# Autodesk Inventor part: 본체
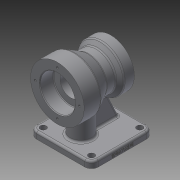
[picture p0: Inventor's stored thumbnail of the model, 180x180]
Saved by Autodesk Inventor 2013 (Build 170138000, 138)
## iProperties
Created: 2019-01
Part Number: 본체
Material: 일반
Document SubType Name: Modeling
Designer: Administrator
Density: 1 g/cm^3
Author: Administrator
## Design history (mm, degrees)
sketch "스케치1"
  geometry: L1 (-30, 0)-(50, 0); L2 (-30, 0)-(-30, 26); L3 (-30, 40)-(-5, 40); L4 (-5, 40)-(15.785, 28); L5 (15.785, 28)-(29.126, 28); L6 (29.126, 28)-(35, 35); L7 (35, 35)-(50, 35); L8 (50, 35)-(50, 20); L9 (-30, 26)-(-10, 26); L10 (-10, 26)-(-10, 16); L11 (-10, 16)-(33, 16); L12 (33, 16)-(33, 20); L13 (33, 20)-(50, 20); L14 (-30, 26)-(-30, 40); L15 (50, 20)-(50, 0); 1 further point
  constraints: 30 end point, 9 perpendicular, 7 parallel, 1 horizontal, 1 point on line
  dimensions: "d0" = 80 distance of L1.start L1.end; "d2" = 80 diameter of L3 L1; "d3" = 30 distance of L1.start point (0, 0); "d4" = 25 distance of L3.start L3.end; "d5" = 52 diameter of L9 L1; "d6" = 20 distance of L2.end L9.end; "d7" = 32 diameter of L11 L1; "d8" = 56 diameter of L5 L1; "d9" = 30 deg angle of L5 L4; "d10" = 50 deg angle of L5 L6; "d11" = 70 diameter of L7 L1; "d12" = 15 distance of L6.end L7.end; "d13" = 40 diameter of L13 L1; "d14" = 17 distance of L12.end L8.end; "d15" = 43 distance of L10.end L11.end
revolve "회전1" sketch "스케치1" stored, may be unused: angle "d16" = 90 deg
sketch "스케치2"
  geometry: C1 r 40 at (0, 0) reference; 1 further point
  constraints: 1 vertical alignment
  dimensions: "d17" = 33 distance of C1.centre point (0, 33)
hole "구멍1" sketch "스케치2" at (0, 33) diameter "d18" = 3.242; stored, may be unused: countersink angle "d22" = 90 deg, drill point angle "d24" = 118 deg; dims "d19" = 9, "d20" = 4, "d21" = 2, "d23" = 11
sketch "스케치3"
  geometry: C1 r 20 at (0, 0) reference; 1 further point
  constraints: 1 vertical alignment
  dimensions: "d28" = 27.5 distance of C1.centre point (0, 27.5)
hole "구멍2" sketch "스케치3" at (0, 27.5) diameter "d29" = 3.242; stored, may be unused: countersink angle "d33" = 90 deg, drill point angle "d35" = 118 deg; dims "d30" = 9, "d31" = 4, "d32" = 2, "d34" = 11
sketch "스케치4"
  geometry: L1 (-25, -70)-(67, -70); L2 (67, -70)-(67, -80); L3 (67, -80)-(-25, -80); L4 (-25, -80)-(-25, -70); 1 further point
  constraints: 8 end point, 2 parallel, 1 horizontal, 1 perpendicular
  dimensions: "d39" = 92 distance of L1.start L1.end; "d41" = 10 distance of L3.end L1.start; "d42" = 80 distance from line of L3 point (0, 0); "d67" = 25 distance from line of point (0, 0) L4
extrude "돌출1" join sketch "스케치4" stored distance "d44" = 92; taper "d45" = 0 deg
fillet "모깎기1" dims "d46" = 10
sketch "스케치5"
  geometry: A1 r 10 centre (72, -10) between (82, -10) and (72, 0) reference; A2 r 10 centre (0, -10) between (0, 0) and (-10, -10) reference; A3 r 10 centre (0, -82) between (-10, -82) and (0, -92) reference; A4 r 10 centre (72, -82) between (72, -92) and (82, -82) reference; 5 further points
  constraints: 4 coincident
hole "구멍3" sketch "스케치5" at (0, -10), (0, -82), (72, -82), (72, -10) diameter "d47" = 9; stored, may be unused: countersink angle "d51" = 90 deg, drill point angle "d53" = 118 deg; dims "d48" = 9, "d49" = 4, "d50" = 2, "d52" = 11
sketch "스케치6"
  geometry: L1 (-10, -10)-(-10, -82) reference; L2 (72, -92)-(0, -92) reference; C1 r 16 at (20, -46); 1 further point
  constraints: 1 centre point
  dimensions: "d68" = 32 diameter of C1; "d70" = 30 distance from line of L1 C1.centre; "d71" = 46 distance from line of C1.centre L2
extrude "돌출2" join sketch "스케치6" stored distance "d56" = 0; taper "d57" = 0 deg
sketch "스케치7"
  geometry: L1 (42.078, -37.999)-(57, -70); L2 (57, -70)-(-15, -70) reference; L3 (67, -80)-(67, -70) reference; L4 (57, -70)-(67, -70) reference; 1 further point
  constraints: 2 end point, 1 point on line
  dimensions: "d58" = 25 deg angle of L1 L3; "d59" = 10 distance from line of L3 L1.end
feature "리브1" sketch "스케치7" dims "d60" = 1, "d61" = 10, "d62" = 0, "d63" = 0, "d64" = 1, "d65" = 1
fillet "모깎기3" dims "d72" = 3
fillet "모깎기4" dims "d73" = 3
fillet "모깎기5" dims "d74" = 3
fillet "모깎기6" dims "d75" = 3
fillet "모깎기7" dims "d76" = 1
fillet "모깎기8" dims "d77" = 0.6
chamfer "모따기1" distance "d78" = 1; stored, may be unused: second distance "d79" = 2, angle "d80" = 45 deg
sketch "스케치8"
  geometry: L1 (-15, -80)-(57, -80) reference; L2 (-25, -73)-(-25, -80) reference; 2 further points
  constraints: 1 other
  dimensions: "d81" = 4 distance from line of L1 point (21, -76); "d82" = 46 distance from line of L2 point (21, -76)
feature "엠보싱1" sketch "스케치8" dims "d17" = 33, "d83" = 0.5, "d84" = 0
node "솔리드1"
pattern_circular "원형 패턴1" dims angle "d26" = 360 deg
pattern_circular "원형 패턴2" dims angle "d37" = 360 deg
